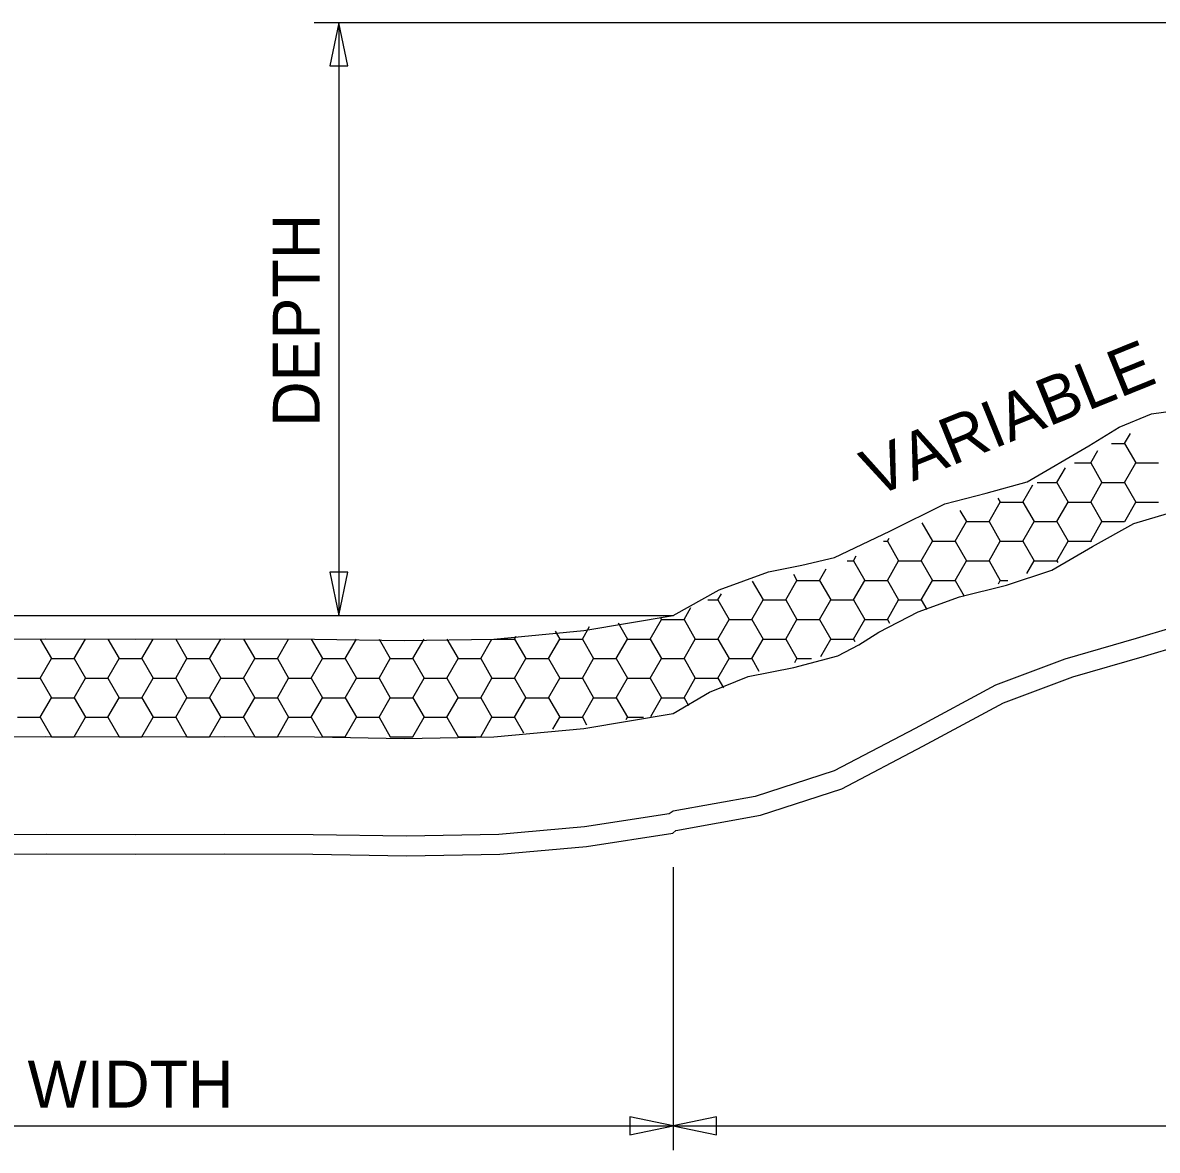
# Model space of a CAD drawing. Extents: x -439.1 to -407.9, y -458.1 to -436.2.
# Drawn here: x -428.281 to -424.656, y -452.73 to -449.128 of the extents above; entities that cross this region are included whole.
import ezdxf

# ---------------------------------------------------------------- set-up
doc = ezdxf.new("R2010")
doc.units = 0
doc.layers.add('Default', color=7, linetype='Continuous')

msp = doc.modelspace()

# ---------------------------------------------------------------- linework, layer by layer
at = {"layer": 'Default'}
for p, q in [((-421.6248, -449.1281), (-427.3495, -449.1281)), ((-427.2714, -449.1281), (-427.2714, -451.0219)), ((-424.7611, -450.4719), (-424.7426, -450.44)), ((-424.8031, -450.4719), (-424.7611, -450.4719)), ((-424.7611, -450.4719), (-424.725, -450.5344)), ((-424.8693, -450.5344), (-424.8464, -450.4948)), ((-424.9776, -450.5969), (-424.9502, -450.5496)), ((-424.9215, -450.5344), (-424.8693, -450.5344)), ((-424.8693, -450.5344), (-424.8332, -450.5969)), ((-424.7611, -450.5969), (-424.725, -450.5344)), ((-424.725, -450.5344), (-424.6528, -450.5344)), ((-425.0858, -450.6594), (-425.054, -450.6044)), ((-425.0399, -450.5969), (-424.9776, -450.5969)), ((-424.9776, -450.5969), (-424.9415, -450.6594)), ((-424.8693, -450.6594), (-424.8332, -450.5969)), ((-424.8332, -450.5969), (-424.7611, -450.5969)), ((-424.7611, -450.5969), (-424.725, -450.6594)), ((-425.1941, -450.7219), (-425.158, -450.6594)), ((-425.1655, -450.6464), (-425.158, -450.6594)), ((-425.158, -450.6594), (-425.0858, -450.6594)), ((-425.0858, -450.6594), (-425.0497, -450.7219)), ((-424.9776, -450.7219), (-424.9415, -450.6594)), ((-424.9415, -450.6594), (-424.8693, -450.6594)), ((-424.8693, -450.6594), (-424.8332, -450.7219)), ((-424.7607, -450.7213), (-424.725, -450.6594)), ((-424.725, -450.6594), (-424.6528, -450.6594)), ((-425.2869, -450.6862), (-425.2663, -450.7219)), ((-425.4083, -450.7259), (-425.3745, -450.7844)), ((-425.3023, -450.7844), (-425.2663, -450.7219)), ((-425.2663, -450.7219), (-425.1941, -450.7219)), ((-425.1941, -450.7219), (-425.158, -450.7844)), ((-425.0858, -450.7844), (-425.0497, -450.7219)), ((-425.0497, -450.7219), (-424.9776, -450.7219)), ((-424.9776, -450.7219), (-424.9415, -450.7844)), ((-424.8693, -450.7844), (-424.8332, -450.7219)), ((-424.8332, -450.7219), (-424.7617, -450.7219)), ((-425.5312, -450.7844), (-425.5188, -450.7844)), ((-425.5188, -450.7844), (-425.5133, -450.7748)), ((-425.5188, -450.7844), (-425.4828, -450.8469)), ((-425.4106, -450.8469), (-425.3745, -450.7844)), ((-425.3745, -450.7844), (-425.3023, -450.7844)), ((-425.3023, -450.7844), (-425.2663, -450.8469)), ((-425.1941, -450.8469), (-425.158, -450.7844)), ((-425.158, -450.7844), (-425.0858, -450.7844)), ((-425.0858, -450.7844), (-425.0497, -450.8469)), ((-424.9776, -450.8469), (-424.9415, -450.7844)), ((-424.9415, -450.7844), (-424.8693, -450.7844)), ((-424.8693, -450.7844), (-424.8679, -450.7868)), ((-425.6271, -450.8469), (-425.618, -450.8312)), ((-425.7353, -450.9094), (-425.7141, -450.8726)), ((-425.6472, -450.8469), (-425.6271, -450.8469)), ((-425.6271, -450.8469), (-425.591, -450.9094)), ((-425.5188, -450.9094), (-425.4828, -450.8469)), ((-425.4828, -450.8469), (-425.4106, -450.8469)), ((-425.4106, -450.8469), (-425.3745, -450.9094)), ((-425.3023, -450.9094), (-425.2663, -450.8469)), ((-425.2663, -450.8469), (-425.1941, -450.8469)), ((-425.1941, -450.8469), (-425.158, -450.9094)), ((-425.0732, -450.8876), (-425.0497, -450.8469)), ((-425.0497, -450.8469), (-424.9776, -450.8469)), ((-424.9776, -450.8469), (-424.9746, -450.852)), ((-425.9506, -450.9116), (-425.9158, -450.9719)), ((-425.8436, -450.9719), (-425.8075, -450.9094)), ((-425.8188, -450.8898), (-425.8075, -450.9094)), ((-425.8075, -450.9094), (-425.7353, -450.9094)), ((-425.7353, -450.9094), (-425.6993, -450.9719)), ((-425.6271, -450.9719), (-425.591, -450.9094)), ((-425.591, -450.9094), (-425.5188, -450.9094)), ((-425.5188, -450.9094), (-425.4828, -450.9719)), ((-425.4106, -450.9719), (-425.3745, -450.9094)), ((-425.3745, -450.9094), (-425.3023, -450.9094)), ((-425.3023, -450.9094), (-425.2733, -450.9596)), ((-425.1643, -450.9204), (-425.158, -450.9094)), ((-425.158, -450.9094), (-425.1339, -450.9094)), ((-426.0601, -450.9719), (-426.049, -450.9526)), ((-426.0918, -450.9719), (-426.0601, -450.9719)), ((-426.0601, -450.9719), (-426.024, -451.0344)), ((-425.9519, -451.0344), (-425.9158, -450.9719)), ((-425.9158, -450.9719), (-425.8436, -450.9719)), ((-425.8436, -450.9719), (-425.8075, -451.0344)), ((-425.7353, -451.0344), (-425.6993, -450.9719)), ((-425.6993, -450.9719), (-425.6271, -450.9719)), ((-425.6271, -450.9719), (-425.591, -451.0344)), ((-425.5188, -451.0344), (-425.4828, -450.9719)), ((-425.4828, -450.9719), (-425.4106, -450.9719)), ((-425.4106, -450.9719), (-425.3927, -451.0029)), ((-429.6399, -451.0216), (-426.2024, -451.0216)), ((-426.1684, -451.0344), (-426.1465, -450.9965)), ((-426.4931, -451.0969), (-426.47, -451.0569)), ((-426.3788, -451.045), (-426.3488, -451.0969)), ((-426.2766, -451.0969), (-426.2405, -451.0344)), ((-426.2446, -451.0274), (-426.2405, -451.0344)), ((-426.2405, -451.0344), (-426.2029, -451.0344)), ((-426.2029, -451.0344), (-426.1684, -451.0344)), ((-426.1684, -451.0344), (-426.1323, -451.0969)), ((-426.0601, -451.0969), (-426.024, -451.0344)), ((-426.024, -451.0344), (-425.9519, -451.0344)), ((-425.9519, -451.0344), (-425.9158, -451.0969)), ((-425.8436, -451.0969), (-425.8075, -451.0344)), ((-425.8075, -451.0344), (-425.7353, -451.0344)), ((-425.7353, -451.0344), (-425.6993, -451.0969)), ((-425.6271, -451.0969), (-425.591, -451.0344)), ((-425.591, -451.0344), (-425.5188, -451.0344)), ((-425.5188, -451.0344), (-425.512, -451.0462)), ((-428.2251, -451.0969), (-428.1891, -451.1594)), ((-428.1169, -451.1594), (-428.0808, -451.0969)), ((-428.0086, -451.0969), (-427.9726, -451.1594)), ((-427.9004, -451.1594), (-427.8643, -451.0969)), ((-427.7921, -451.0969), (-427.7561, -451.1594)), ((-427.6839, -451.1594), (-427.6478, -451.0969)), ((-427.5756, -451.0969), (-427.5396, -451.1594)), ((-427.4674, -451.1594), (-427.4313, -451.0969)), ((-427.3591, -451.0969), (-427.3231, -451.1594)), ((-427.2509, -451.1594), (-427.2148, -451.0969)), ((-427.1426, -451.0969), (-427.1066, -451.1594)), ((-427.0344, -451.1594), (-426.9983, -451.0969)), ((-426.9261, -451.0969), (-426.89, -451.1594)), ((-426.8179, -451.1594), (-426.7818, -451.0969)), ((-426.7756, -451.0969), (-426.7096, -451.0969)), ((-426.7096, -451.0969), (-426.7042, -451.0876)), ((-426.7096, -451.0969), (-426.6735, -451.1594)), ((-426.6014, -451.1594), (-426.5653, -451.0969)), ((-426.5801, -451.0713), (-426.5653, -451.0969)), ((-426.5653, -451.0969), (-426.4931, -451.0969)), ((-426.4931, -451.0969), (-426.457, -451.1594)), ((-426.3849, -451.1594), (-426.3488, -451.0969)), ((-426.3488, -451.0969), (-426.2766, -451.0969)), ((-426.2766, -451.0969), (-426.2405, -451.1594)), ((-426.1684, -451.1594), (-426.1323, -451.0969)), ((-426.1323, -451.0969), (-426.0601, -451.0969)), ((-426.0601, -451.0969), (-426.024, -451.1594)), ((-425.9519, -451.1594), (-425.9158, -451.0969)), ((-425.9158, -451.0969), (-425.8436, -451.0969)), ((-425.8436, -451.0969), (-425.8075, -451.1594)), ((-425.7312, -451.1522), (-425.6993, -451.0969)), ((-425.6993, -451.0969), (-425.6271, -451.0969)), ((-425.6271, -451.0969), (-425.6225, -451.1049)), ((-428.2252, -451.2219), (-428.1891, -451.1594)), ((-428.1891, -451.1594), (-428.1169, -451.1594)), ((-428.1169, -451.1594), (-428.0808, -451.2219)), ((-428.0087, -451.2219), (-427.9726, -451.1594)), ((-427.9726, -451.1594), (-427.9004, -451.1594)), ((-427.9004, -451.1594), (-427.8643, -451.2219)), ((-427.7922, -451.2219), (-427.7561, -451.1594)), ((-427.7561, -451.1594), (-427.6839, -451.1594)), ((-427.6839, -451.1594), (-427.6478, -451.2219)), ((-427.5756, -451.2219), (-427.5396, -451.1594)), ((-427.5396, -451.1594), (-427.4674, -451.1594)), ((-427.4674, -451.1594), (-427.4313, -451.2219)), ((-427.3591, -451.2219), (-427.3231, -451.1594)), ((-427.3231, -451.1594), (-427.2509, -451.1594)), ((-427.2509, -451.1594), (-427.2148, -451.2219)), ((-427.1426, -451.2219), (-427.1066, -451.1594)), ((-427.1066, -451.1594), (-427.0344, -451.1594)), ((-427.0344, -451.1594), (-426.9983, -451.2219)), ((-426.9261, -451.2219), (-426.89, -451.1594)), ((-426.89, -451.1594), (-426.8179, -451.1594)), ((-426.8179, -451.1594), (-426.7818, -451.2219)), ((-426.7096, -451.2219), (-426.6735, -451.1594)), ((-426.6735, -451.1594), (-426.6014, -451.1594)), ((-426.6014, -451.1594), (-426.5653, -451.2219)), ((-426.4931, -451.2219), (-426.457, -451.1594)), ((-426.457, -451.1594), (-426.3849, -451.1594)), ((-426.3849, -451.1594), (-426.3488, -451.2219)), ((-426.2766, -451.2219), (-426.2405, -451.1594)), ((-426.2405, -451.1594), (-426.2029, -451.1594)), ((-426.2029, -451.1594), (-426.1684, -451.1594)), ((-426.1684, -451.1594), (-426.1323, -451.2219)), ((-426.0601, -451.2219), (-426.024, -451.1594)), ((-426.024, -451.1594), (-425.9519, -451.1594)), ((-425.9519, -451.1594), (-425.929, -451.199)), ((-425.8148, -451.172), (-425.8075, -451.1594)), ((-425.8075, -451.1594), (-425.7616, -451.1594)), ((-428.2973, -451.2219), (-428.2252, -451.2219)), ((-428.2252, -451.2219), (-428.1891, -451.2844)), ((-428.1169, -451.2844), (-428.0808, -451.2219)), ((-428.0808, -451.2219), (-428.0087, -451.2219)), ((-428.0087, -451.2219), (-427.9726, -451.2844)), ((-427.9004, -451.2844), (-427.8643, -451.2219)), ((-427.8643, -451.2219), (-427.7922, -451.2219)), ((-427.7922, -451.2219), (-427.7561, -451.2844)), ((-427.6839, -451.2844), (-427.6478, -451.2219)), ((-427.6478, -451.2219), (-427.5756, -451.2219)), ((-427.5756, -451.2219), (-427.5396, -451.2844)), ((-427.4674, -451.2844), (-427.4313, -451.2219)), ((-427.4313, -451.2219), (-427.3591, -451.2219)), ((-427.3591, -451.2219), (-427.3231, -451.2844)), ((-427.2509, -451.2844), (-427.2148, -451.2219)), ((-427.2148, -451.2219), (-427.1426, -451.2219)), ((-427.1426, -451.2219), (-427.1066, -451.2844)), ((-427.0344, -451.2844), (-426.9983, -451.2219)), ((-426.9983, -451.2219), (-426.9261, -451.2219)), ((-426.9261, -451.2219), (-426.89, -451.2844)), ((-426.8179, -451.2844), (-426.7818, -451.2219)), ((-426.7818, -451.2219), (-426.7096, -451.2219)), ((-426.7096, -451.2219), (-426.6735, -451.2844)), ((-426.6014, -451.2844), (-426.5653, -451.2219)), ((-426.5653, -451.2219), (-426.4931, -451.2219)), ((-426.4931, -451.2219), (-426.457, -451.2844)), ((-426.3849, -451.2844), (-426.3488, -451.2219)), ((-426.3488, -451.2219), (-426.2766, -451.2219)), ((-426.2766, -451.2219), (-426.2405, -451.2844)), ((-426.1684, -451.2844), (-426.1323, -451.2219)), ((-426.1323, -451.2219), (-426.0601, -451.2219)), ((-426.0601, -451.2219), (-426.0421, -451.2532)), ((-428.2252, -451.3469), (-428.1891, -451.2844)), ((-428.1891, -451.2844), (-428.1169, -451.2844)), ((-428.1169, -451.2844), (-428.0808, -451.3469)), ((-428.0087, -451.3469), (-427.9726, -451.2844)), ((-427.9726, -451.2844), (-427.9004, -451.2844)), ((-427.9004, -451.2844), (-427.8643, -451.3469)), ((-427.7922, -451.3469), (-427.7561, -451.2844)), ((-427.7561, -451.2844), (-427.6839, -451.2844)), ((-427.6839, -451.2844), (-427.6478, -451.3469)), ((-427.5756, -451.3469), (-427.5396, -451.2844)), ((-427.5396, -451.2844), (-427.4674, -451.2844)), ((-427.4674, -451.2844), (-427.4313, -451.3469)), ((-427.3591, -451.3469), (-427.3231, -451.2844)), ((-427.3231, -451.2844), (-427.2509, -451.2844)), ((-427.2509, -451.2844), (-427.2148, -451.3469)), ((-427.1426, -451.3469), (-427.1066, -451.2844)), ((-427.1066, -451.2844), (-427.0344, -451.2844)), ((-427.0344, -451.2844), (-426.9983, -451.3469)), ((-426.9261, -451.3469), (-426.89, -451.2844)), ((-426.89, -451.2844), (-426.8179, -451.2844)), ((-426.8179, -451.2844), (-426.7818, -451.3469)), ((-426.7096, -451.3469), (-426.6735, -451.2844)), ((-426.6735, -451.2844), (-426.6014, -451.2844)), ((-426.6014, -451.2844), (-426.5653, -451.3469)), ((-426.4931, -451.3469), (-426.457, -451.2844)), ((-426.457, -451.2844), (-426.3849, -451.2844)), ((-426.3849, -451.2844), (-426.3488, -451.3469)), ((-426.2748, -451.3439), (-426.2405, -451.2844)), ((-426.2405, -451.2844), (-426.2029, -451.2844)), ((-426.2029, -451.2844), (-426.1684, -451.2844)), ((-426.1684, -451.2844), (-426.1538, -451.3096)), ((-428.2973, -451.3469), (-428.2252, -451.3469)), ((-428.2252, -451.3469), (-428.1891, -451.4094)), ((-428.1169, -451.4094), (-428.0808, -451.3469)), ((-428.0808, -451.3469), (-428.0087, -451.3469)), ((-428.0087, -451.3469), (-427.9726, -451.4094)), ((-427.9004, -451.4094), (-427.8643, -451.3469)), ((-427.8643, -451.3469), (-427.7922, -451.3469)), ((-427.7922, -451.3469), (-427.7561, -451.4094)), ((-427.6839, -451.4094), (-427.6478, -451.3469)), ((-427.6478, -451.3469), (-427.5756, -451.3469)), ((-427.5756, -451.3469), (-427.5396, -451.4094)), ((-427.4674, -451.4094), (-427.4313, -451.3469)), ((-427.4313, -451.3469), (-427.3591, -451.3469)), ((-427.3591, -451.3469), (-427.3231, -451.4094)), ((-427.2509, -451.4094), (-427.2148, -451.3469)), ((-427.2148, -451.3469), (-427.1426, -451.3469)), ((-427.1426, -451.3469), (-427.1066, -451.4094)), ((-427.0344, -451.4094), (-426.9983, -451.3469)), ((-426.9983, -451.3469), (-426.9261, -451.3469)), ((-426.9261, -451.3469), (-426.89, -451.4094)), ((-426.8179, -451.4094), (-426.7818, -451.3469)), ((-426.7818, -451.3469), (-426.7096, -451.3469)), ((-426.7096, -451.3469), (-426.6807, -451.397)), ((-426.5871, -451.3848), (-426.5653, -451.3469)), ((-426.5653, -451.3469), (-426.4931, -451.3469)), ((-426.4931, -451.3469), (-426.4794, -451.3706)), ((-426.3529, -451.3541), (-426.3488, -451.3469)), ((-426.3488, -451.3469), (-426.2982, -451.3469)), ((-428.1891, -451.4094), (-428.1169, -451.4094)), ((-428.1891, -451.4094), (-428.1891, -451.4094)), ((-428.1169, -451.4094), (-428.1169, -451.4094)), ((-427.9726, -451.4094), (-427.9004, -451.4094)), ((-427.9726, -451.4094), (-427.9726, -451.4094)), ((-427.9004, -451.4094), (-427.9004, -451.4094)), ((-427.7561, -451.4094), (-427.6839, -451.4094)), ((-427.7561, -451.4094), (-427.7561, -451.4094)), ((-427.6839, -451.4094), (-427.6839, -451.4094)), ((-427.5396, -451.4094), (-427.4674, -451.4094)), ((-427.5396, -451.4094), (-427.5396, -451.4094)), ((-427.4674, -451.4094), (-427.4674, -451.4094)), ((-427.3231, -451.4094), (-427.2509, -451.4094)), ((-427.3231, -451.4094), (-427.3231, -451.4094)), ((-427.2509, -451.4094), (-427.2509, -451.4094)), ((-427.1066, -451.4094), (-427.0344, -451.4094)), ((-427.1066, -451.4094), (-427.1066, -451.4094)), ((-427.0344, -451.4094), (-427.0344, -451.4094)), ((-426.8901, -451.4094), (-426.89, -451.4094)), ((-426.89, -451.4094), (-426.8179, -451.4094)), ((-426.8179, -451.4094), (-426.8179, -451.4094)), ((-426.2029, -451.6469), (-426.2155, -451.655)), ((-426.2044, -451.7165), (-426.1945, -451.7089)), ((-426.2029, -451.8256), (-426.2029, -452.73)), ((-429.6404, -452.6519), (-426.2029, -452.6519)), ((-426.2029, -452.6519), (-421.5154, -452.6519))]:
    msp.add_line(p, q, dxfattribs=at)
for points in [[(-427.2427, -449.2664), (-427.2714, -449.1281), (-427.3001, -449.2664)], [(-427.3001, -450.8836), (-427.2714, -451.0219), (-427.2427, -450.8836)], [(-426.3412, -452.6806), (-426.2029, -452.6519), (-426.3412, -452.6232)], [(-426.0646, -452.6232), (-426.2029, -452.6519), (-426.0646, -452.6806)]]:
    msp.add_lwpolyline(points, close=True, dxfattribs=at)
for points in [[(-421.5154, -449.7531), (-421.7919, -449.8866), (-422.0715, -450.0146), (-422.4758, -450.1931), (-422.6825, -450.2698), (-422.8948, -450.3305), (-423.1947, -450.3895), (-423.3427, -450.4223), (-423.4856, -450.4672), (-423.6898, -450.5682), (-423.8842, -450.6944), (-424.0772, -450.8253), (-424.2775, -450.9404), (-424.4965, -451.0275), (-424.7242, -451.0948), (-424.9524, -451.1609), (-425.1732, -451.244), (-425.4303, -451.3824), (-425.6888, -451.5176), (-425.941, -451.5994), (-426.2029, -451.6469)], [(-426.1945, -451.7089), (-425.9244, -451.6596), (-425.6642, -451.575), (-425.405, -451.4395), (-425.1473, -451.3009), (-424.9261, -451.2176), (-424.6975, -451.1513), (-424.4695, -451.0838), (-424.2501, -450.9967), (-424.051, -450.8821), (-423.8592, -450.7517), (-423.6661, -450.6261), (-423.4632, -450.5256), (-423.3223, -450.4813), (-423.1763, -450.4492), (-422.8805, -450.3913), (-422.6652, -450.3299), (-422.4555, -450.2522), (-422.0455, -450.0714), (-421.7648, -449.9429), (-421.4426, -449.7873)], [(-426.2029, -451.0219), (-426.0559, -450.9399), (-425.8984, -450.8821), (-425.7922, -450.861), (-425.6877, -450.8367), (-425.5112, -450.752), (-425.3351, -450.6645), (-425.203, -450.6305), (-425.072, -450.5943), (-424.8753, -450.4797), (-424.7783, -450.4199), (-424.6753, -450.378), (-424.5453, -450.3598)], [(-426.2029, -451.3344), (-426.087, -451.267), (-425.9631, -451.2168), (-425.8177, -451.1881), (-425.6766, -451.1507), (-425.6104, -451.1153), (-425.5458, -451.0749), (-425.4207, -451.0099), (-425.2882, -450.962), (-425.1384, -450.9246), (-424.9935, -450.8766), (-424.8631, -450.8011), (-424.7318, -450.7279), (-424.5847, -450.6846)], [(-429.6404, -451.0219), (-429.3552, -451.0697), (-429.0675, -451.0969), (-428.7812, -451.1016), (-428.4946, -451.0969), (-428.2081, -451.096), (-427.9217, -451.0969), (-427.6353, -451.096), (-427.3487, -451.0969), (-427.0621, -451.1016), (-426.7758, -451.0969), (-426.4881, -451.0697), (-426.2029, -451.0219)], [(-429.6404, -451.3344), (-429.3552, -451.3822), (-429.0675, -451.4094), (-428.7812, -451.4141), (-428.4946, -451.4094), (-428.2081, -451.4085), (-427.9217, -451.4094), (-427.6353, -451.4085), (-427.3487, -451.4094), (-427.0621, -451.4141), (-426.7758, -451.4094), (-426.4881, -451.3822), (-426.2029, -451.3344)], [(-426.2155, -451.655), (-426.4866, -451.6971), (-426.7596, -451.7215), (-427.056, -451.7265), (-427.3528, -451.7219), (-427.6373, -451.721), (-427.9217, -451.7219), (-428.206, -451.721), (-428.4905, -451.7219), (-428.7873, -451.7265), (-429.0837, -451.7215), (-429.3591, -451.6968), (-429.6296, -451.6546)], [(-429.6536, -451.7141), (-429.3663, -451.7589), (-429.087, -451.7839), (-428.7885, -451.789), (-428.4897, -451.7844), (-428.2056, -451.7835), (-427.9217, -451.7844), (-427.6377, -451.7835), (-427.3536, -451.7844), (-427.0548, -451.789), (-426.7563, -451.7839), (-426.4794, -451.7592), (-426.2044, -451.7165)]]:
    msp.add_lwpolyline(points, dxfattribs=at)

# ---------------------------------------------------------------- texts
for s, rotation, p in [('DEPTH', 90, (-427.332, -450.4188)), ('VARIABLE', 22, (-425.5618, -450.6444))]:
    msp.add_text(s, height=0.15, rotation=rotation, dxfattribs=at).set_placement(p)
msp.add_text('WIDTH', height=0.15, dxfattribs=at).set_placement((-428.2654, -452.5936))

doc.saveas('drawing.dxf')
